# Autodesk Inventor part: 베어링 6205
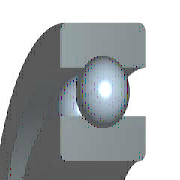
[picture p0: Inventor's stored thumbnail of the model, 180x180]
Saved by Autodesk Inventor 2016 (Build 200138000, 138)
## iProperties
Created: 2015-10
Part Number: 베어링 6205
Material: 강, 연강
Description: 깊은 그루브 볼 베어링
Document SubType Name: Modeling
Standard: KS B 2023
Designer: mdu
Standards Organization: KS
Language: ko-KR
Size Designation: 6205 - 25 x 52 x 15
Categories: <MemberInstance><Categories><Category DisplayName="샤프트 부품" InternalName="7f7aeb1f-a693-4053-b835-cee3144e0d98" Mnemonic="SHFT"><Category DisplayName="베어링" Inter
Density: 7.85 g/cm^3
Appearance: 강철
Mass: 129.378 g
Surface Area: 107.326 cm^2
Volume: 16.4813 cm^3
IsCustomPart: 1
Author: mdu
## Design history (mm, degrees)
sketch "스케치" dims "d0" = 7.02 (= -0.26 x WD + 0.26 x BD)
  geometry: L1 (3.99, 19.25)-(11.01, 19.25); L2 (7.5, 19.25)-(7.5, 15.74); L3 (7.5, 19.25)-(7.5, 22.76); L4 (4.892, 16.901)-(0, 16.901); L5 (0, 12.5)-(15, 12.5); L6 (4.892, 21.599)-(0, 21.599); L7 (0, 26)-(15, 26); L8 (15, 12.5)-(15, 16.901); L9 (10.108, 16.901)-(15, 16.901); L10 (10.108, 21.599)-(15, 21.599); L11 (15, 26)-(15, 21.599); L12 (-1.4, 0)-(8.4, 0) reference; L13 (0, -0.3)-(0, 5.3) reference
  constraints: 22 end point, 4 point on line, 2 collinear, 2 perpendicular, 2 symmetric about line, 1 midpoint, 1 parallel, 14 other
  dimensions: "d9" = 25 diameter of L5 L12 (= WD); "d11" = 52 diameter of L7 L12 (= BD); "d12" = 15 distance between parallel lines of L8 L13 (= KB); "d13" = 33.802 diameter of L9 L12 (= 0.326 x BD + 0.674 x WD)
revolve "본체" stored, may be unused: angle "d6" = 90 deg
revolve "볼" stored, may be unused: angle "d7" = 90 deg
pattern_circular "IDS_ARRAYBALL[SIMPL:T]" dims angle "d3" = 360 deg
body "Solid1"
fillet "모깎기1" dims "d1" = 1 (= KRS)
other parameters: "WD" = 25 [user parameter; used in 5 equation terms], "BD" = 52 [user parameter; used in 5 equation terms], "KB" = 15 [user parameter; used in 1 equation term], "KRS" = 1 [user parameter; used in 1 equation term], "d4" = 0, "d5" = 0, "d8" = 0, "d14" = 0, "d15" = 0, "BBA" = 0 [user parameter], "BC0" = 7800000 [user parameter], "BC" = 1.4e+07 [user parameter], "BR" = 26 (= 0.5 x BD) [user parameter], "WR" = 12.5 (= 0.5 x WD) [user parameter]
